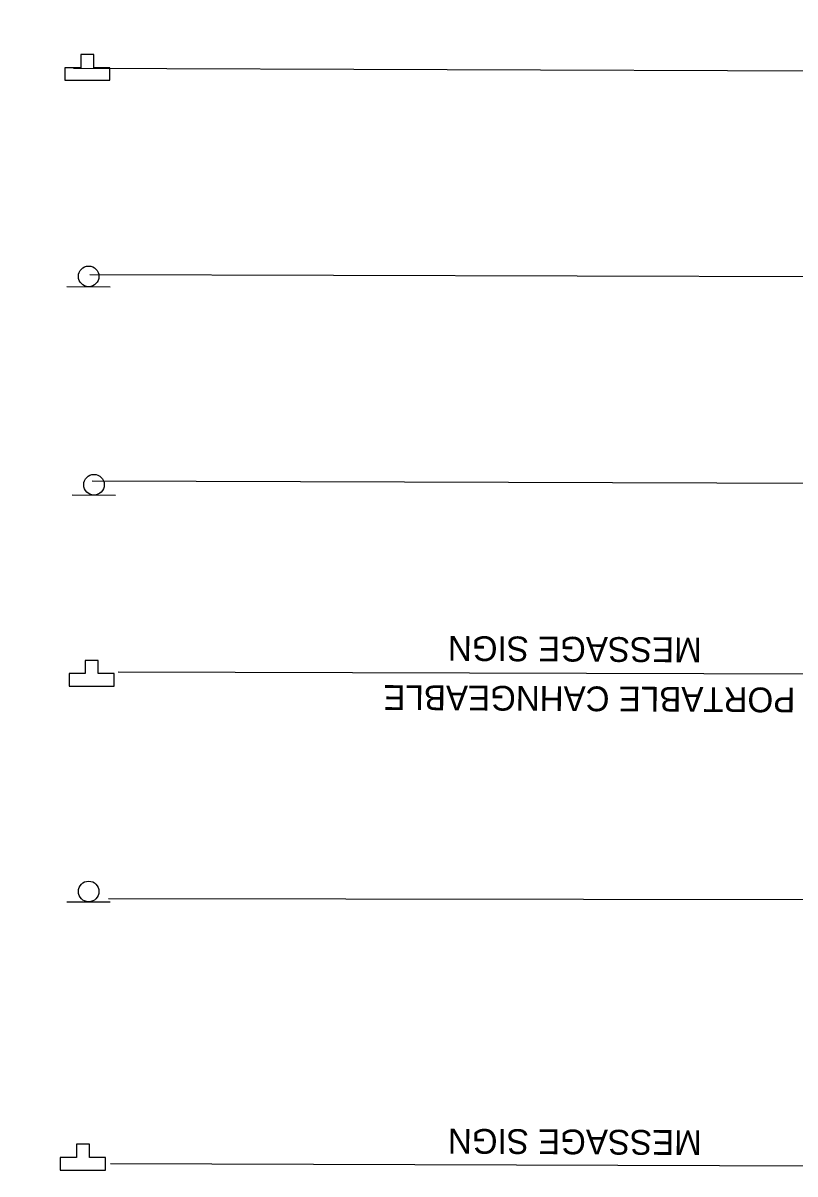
# Model space of a CAD drawing. Extents: x 2135767 to 2151731, y 141839 to 175894.
# Drawn here: x 2140472.6 to 2140659.8, y 168318.8 to 168597.8 of the extents above; entities that cross this region are included whole.
import ezdxf

# ---------------------------------------------------------------- set-up
doc = ezdxf.new("R2010")
doc.units = 0
for name, color, linetype in [('Default', 7, 'Continuous'), ('PR_Dimensions_Phase', 7, 'Continuous'), ('PR_Phasing_Detour_1', 7, 'Continuous'), ('PR_Traffic_Control_Devices_Temp', 7, 'Continuous')]:
    doc.layers.add(name, color=color, linetype=linetype)

# ---------------------------------------------------------------- blocks, each defined once
blk = doc.blocks.new('PR-TCSIGN_rev')
at = {"layer": 'Default'}
blk.add_lwpolyline([(-5.47, 0), (-1.58, 0), (-1.58, -3.22), (1.58, -3.22), (1.58, 0), (5.47, 0), (5.47, 3.06), (-5.47, 3.06)], close=True, dxfattribs=at)
blk.add_lwpolyline([(1.58, 0), (5.47, 0), (5.47, 3.06), (-5.47, 3.06), (-5.47, 0), (-1.58, 0), (-1.58, -3.22), (1.58, -3.22), (1.58, 0)], dxfattribs=at)
blk = doc.blocks.new('PR-TCSIGN')
at = {"layer": 'Default'}
blk.add_line((17.82, 8.47), (-17.82, 8.47), dxfattribs=at)
blk.add_circle((0, 0), 8.47, dxfattribs=at)

msp = doc.modelspace()

# ---------------------------------------------------------------- linework, layer by layer
at = {"layer": 'PR_Dimensions_Phase'}
for p, q in [((2140484.8, 168586.83), (2140781.34, 168585.82)), ((2140488.83, 168536.83), (2140698.16, 168536.23)), ((2140489.39, 168486.84), (2140782.81, 168485.8)), ((2140495.66, 168440.53), (2140728.93, 168439.86)), ((2140493.35, 168385.56), (2140802.07, 168385.14)), ((2140493.81, 168321.29), (2140738.75, 168320.54))]:
    msp.add_line(p, q, dxfattribs=at)
at = {"layer": 'PR_Phasing_Detour_1'}
msp.add_circle((2140069.54, 171591.41), 4302.23, dxfattribs=at)

# ---------------------------------------------------------------- block references
at = {"layer": 'PR_Traffic_Control_Devices_Temp', "rotation": 180}
for p in [(2140488.19, 168586.98), (2140489.26, 168440.08), (2140487.11, 168322.78)]:
    msp.add_blockref('PR-TCSIGN_rev', p, dxfattribs=at)
at = {"layer": 'PR_Traffic_Control_Devices_Temp', "xscale": 0.2952750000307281, "yscale": 0.2952750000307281, "rotation": 179.6349826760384}
for p in [(2140488.51, 168536.39), (2140489.8, 168485.87), (2140488.51, 168387.26)]:
    msp.add_blockref('PR-TCSIGN', p, dxfattribs=at)

# ---------------------------------------------------------------- texts
at = {"layer": 'Default'}
for s, p in [('MESSAGE SIGN', (2140637.18, 168448.8)), ('PORTABLE CAHNGEABLE', (2140659.87, 168436.66)), ('MESSAGE SIGN', (2140637.18, 168329.35))]:
    msp.add_text(s, height=6, rotation=179.635, dxfattribs=at).set_placement(p)

doc.saveas('drawing.dxf')
